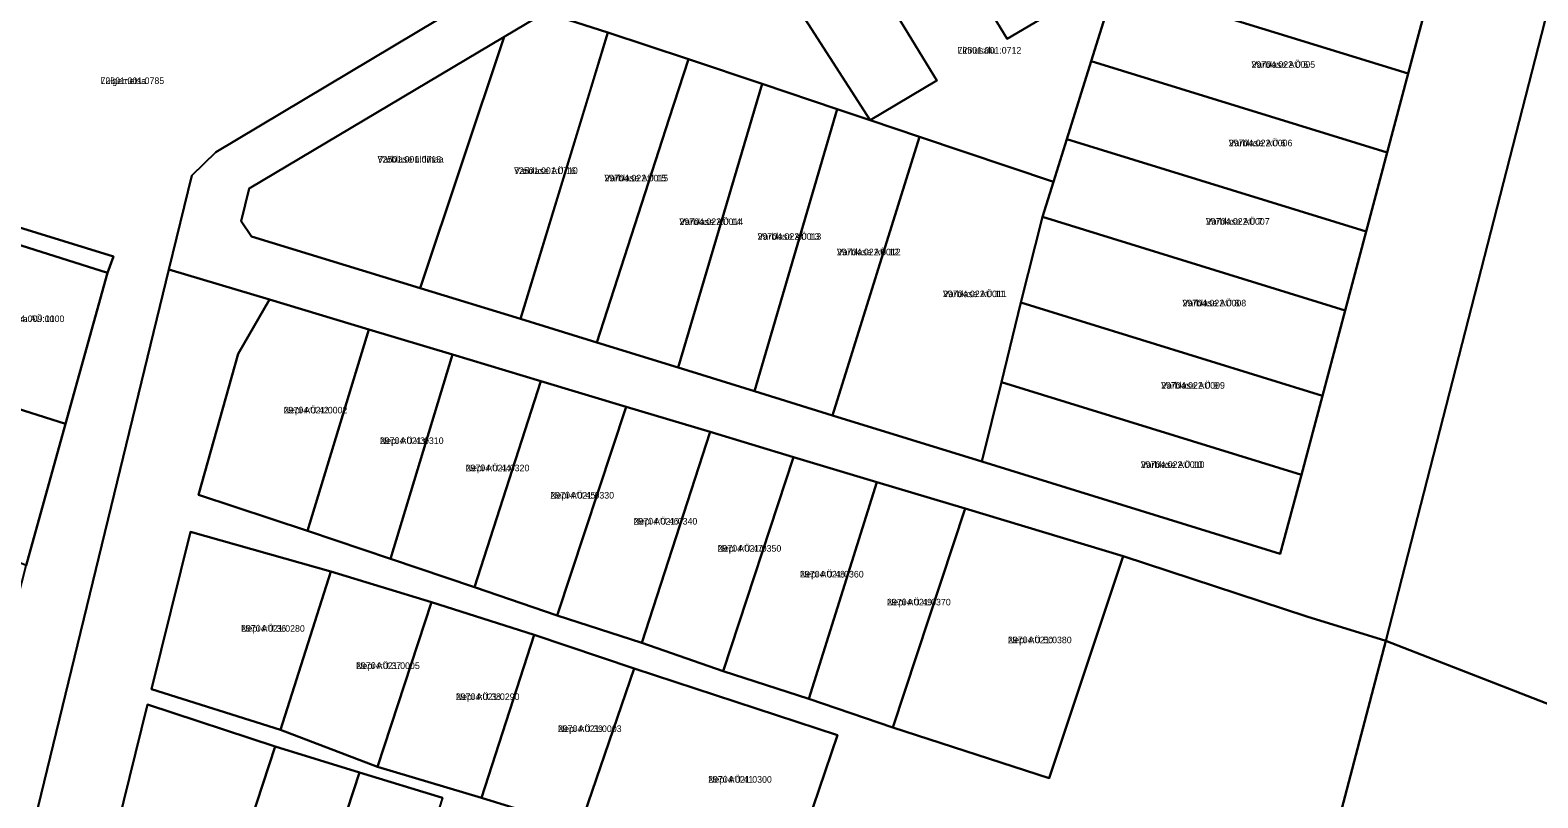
# Model space of a CAD drawing. Extents: x 504287 to 537970, y 6539941 to 6586214.
# Drawn here: x 515935.2 to 516278.4, y 6563085.5 to 6563260.2 of the extents above; entities that cross this region are included whole.
import ezdxf

# ---------------------------------------------------------------- set-up
doc = ezdxf.new("R2010")
doc.units = 0
for name, color, linetype in [('L_AADRESS', 7, 'Continuous'), ('PIIR', 7, 'Continuous'), ('TUNNUS', 7, 'Continuous')]:
    doc.layers.add(name, color=color, linetype=linetype)

msp = doc.modelspace()

# ---------------------------------------------------------------- linework, layer by layer
at = {"layer": 'PIIR'}
for points in [[(515972.01, 6563227.18), (515977.46, 6563232.44), (516073.64, 6563289.98), (516050.45, 6563297.65), (516073.73, 6563311.23), (516084.26, 6563317.42), (516122.11, 6563339.48), (516146.05, 6563353.34), (516182.38, 6563374.75), (516207.94, 6563366.8), (516299.43, 6563338.16), (516243.75, 6563121.25), (516225.77, 6563126.81), (516183.96, 6563140.52), (516148, 6563151.33), (516127.9, 6563157.37), (516108.91, 6563163.08), (516089.94, 6563168.78), (516070.84, 6563174.52), (516051.46, 6563180.35), (516031.31, 6563186.4), (516012.25, 6563192.13), (515989.69, 6563198.92), (515966.79, 6563205.76)], [(516299.43, 6563338.16), (516320.7, 6563333.13), (516451.55, 6563103.15), (516401.08, 6563060.05), (516243.75, 6563121.25)], [(516073.64, 6563289.98), (515977.46, 6563232.44), (515972.01, 6563227.18), (515966.79, 6563205.76), (515909.97, 6562972.61), (515893.26, 6562974.94), (515902.53, 6563013.27), (515910.51, 6563045.99), (515918.12, 6563075.85), (515920.24, 6563083.98), (515927.25, 6563111.02), (515934.26, 6563138.36), (515943.25, 6563170.65), (515952.8, 6563204.98), (515954.15, 6563208.7), (515828.79, 6563247.37), (515836.63, 6563271.97), (515845.75, 6563300.51), (515851.71, 6563319.17), (515917.69, 6563297.46), (515956.39, 6563284.6), (515969.65, 6563324.42), (516015.82, 6563309.11), (516050.45, 6563297.65)], [(516142.3, 6563318.97), (516173.58, 6563267.75), (516157.59, 6563258.26), (516126.3, 6563309.48)], [(516173.58, 6563267.75), (516182.26, 6563270.92), (516176.71, 6563253.19), (516171.16, 6563235.45), (516168.1, 6563225.67), (516137.61, 6563235.94), (516126.37, 6563239.73), (516141.59, 6563248.77), (516110.32, 6563299.97), (516126.3, 6563309.48), (516157.59, 6563258.26)], [(516110.32, 6563299.97), (516141.59, 6563248.77), (516126.37, 6563239.73), (516093.94, 6563290.28)], [(516126.37, 6563239.73), (516118.86, 6563242.26), (516101.78, 6563248.01), (516085.03, 6563253.65), (516066.7, 6563259.68), (516052.39, 6563264.24), (516050.99, 6563264.69), (516093.94, 6563290.28)], [(516253.63, 6563268.32), (516248.84, 6563250.35), (516182.26, 6563270.92), (516183.02, 6563273.35), (516187.81, 6563288.66)], [(516248.84, 6563250.35), (516244.06, 6563232.38), (516176.71, 6563253.19), (516182.26, 6563270.92)], [(516043.06, 6563258.69), (516052.39, 6563264.24), (516066.7, 6563259.68), (516046.78, 6563194.5), (516023.98, 6563201.49)], [(516023.98, 6563201.49), (515985.56, 6563213.28), (515983.2, 6563216.76), (515985.02, 6563224.15), (516043.06, 6563258.69)], [(516062.43, 6563245.69), (516066.7, 6563259.68), (516085.03, 6563253.65), (516080.65, 6563240.11), (516064.16, 6563189.14), (516046.78, 6563194.5)], [(516101.78, 6563248.01), (516082.66, 6563183.42), (516064.16, 6563189.14), (516080.65, 6563240.11), (516085.03, 6563253.65)], [(516244.06, 6563232.38), (516239.27, 6563214.4), (516171.16, 6563235.45), (516176.71, 6563253.19)], [(515828.79, 6563247.37), (515954.15, 6563208.7), (515952.8, 6563204.98), (515915.08, 6563216.94), (515873.94, 6563229.21), (515830.44, 6563242.46), (515826.37, 6563240.09), (515826.78, 6563241.11)], [(516118.86, 6563242.26), (516100.05, 6563178.05), (516082.66, 6563183.42), (516101.78, 6563248.01)], [(516126.37, 6563239.73), (516137.61, 6563235.94), (516117.82, 6563172.56), (516100.05, 6563178.05), (516118.86, 6563242.26)], [(516168.1, 6563225.67), (516165.61, 6563217.71), (516160.72, 6563198.21), (516156.25, 6563180.14), (516151.78, 6563162.06), (516117.82, 6563172.56), (516137.61, 6563235.94)], [(516239.27, 6563214.4), (516234.48, 6563196.43), (516165.61, 6563217.71), (516168.1, 6563225.67), (516171.16, 6563235.45)], [(515903.76, 6563183.26), (515912.83, 6563210.34), (515915.08, 6563216.94), (515952.8, 6563204.98), (515943.25, 6563170.65), (515904.96, 6563182.76)], [(516234.48, 6563196.43), (516229.31, 6563177.01), (516160.72, 6563198.21), (516165.61, 6563217.71)], [(515982.51, 6563186.6), (515989.69, 6563198.92), (516012.25, 6563192.13), (515998.3, 6563146.25), (515973.55, 6563154.51)], [(516229.31, 6563177.01), (516224.53, 6563159.04), (516156.25, 6563180.14), (516160.72, 6563198.21)], [(516012.25, 6563192.13), (516031.31, 6563186.4), (516017.19, 6563139.95), (515998.3, 6563146.25)], [(516031.31, 6563186.4), (516051.46, 6563180.35), (516036.36, 6563133.5), (516017.19, 6563139.95)], [(515914.03, 6563153.48), (515896.73, 6563159.59), (515904.96, 6563182.76), (515943.25, 6563170.65), (515934.26, 6563138.36), (515912.05, 6563147.73)], [(516051.46, 6563180.35), (516070.84, 6563174.52), (516055.15, 6563127.03), (516036.36, 6563133.5)], [(516224.53, 6563159.04), (516219.74, 6563141.07), (516151.78, 6563162.06), (516156.25, 6563180.14)], [(516070.84, 6563174.52), (516089.94, 6563168.78), (516074.41, 6563120.82), (516055.15, 6563127.03)], [(516074.41, 6563120.82), (516089.94, 6563168.78), (516108.91, 6563163.08), (516092.93, 6563114.38)], [(516108.91, 6563163.08), (516127.9, 6563157.37), (516112.44, 6563108.05), (516092.93, 6563114.38)], [(516127.9, 6563157.37), (516148, 6563151.33), (516131.54, 6563101.5), (516112.44, 6563108.05)], [(516148, 6563151.33), (516183.96, 6563140.52), (516167.16, 6563089.97), (516131.54, 6563101.5)], [(515971.71, 6563146.04), (516003.6, 6563137.04), (515992.2, 6563101.02), (515962.81, 6563110.27)], [(516060.23, 6563078.65), (516106.42, 6563062.93), (516118.95, 6563099.81), (516072.69, 6563114.98), (516049.92, 6563122.63), (516026.55, 6563130.04), (516003.6, 6563137.04), (515971.71, 6563146.04), (515962.81, 6563110.27), (515992.2, 6563101.02), (516014.24, 6563092.56), (516037.93, 6563085.55)], [(516003.6, 6563137.04), (516026.55, 6563130.04), (516014.24, 6563092.56), (515992.2, 6563101.02)], [(516026.55, 6563130.04), (516049.92, 6563122.63), (516037.93, 6563085.55), (516014.24, 6563092.56)], [(516049.92, 6563122.63), (516072.69, 6563114.98), (516060.23, 6563078.65), (516037.93, 6563085.55)], [(516131.28, 6562691.84), (516162.69, 6562811.97), (516169.98, 6562839.87), (516172.18, 6562848.28), (516181.49, 6562883.88), (516243.75, 6563121.25), (516401.08, 6563060.05), (516451.55, 6563103.15), (516460.76, 6563084.69), (516429.36, 6563057.64), (516384.12, 6562938.53), (516358.44, 6562814.78), (516531.81, 6562754.14), (516289.98, 6562584.24), (516210.37, 6562653.1)], [(516072.69, 6563114.98), (516118.95, 6563099.81), (516106.42, 6563062.93), (516060.23, 6563078.65)], [(515961.94, 6563106.73), (515990.96, 6563097.2), (515976.94, 6563054.33), (515951.02, 6563062.48)], [(515990.96, 6563097.2), (516010.19, 6563091.3), (515996.15, 6563048.45), (515976.94, 6563054.33)], [(516010.19, 6563091.3), (516029.02, 6563085.5), (516015.32, 6563043.05), (515996.15, 6563048.45)]]:
    msp.add_lwpolyline(points, close=True, dxfattribs=at)
for points in [[(516052.39, 6563264.24), (516043.06, 6563258.69), (515985.02, 6563224.15), (515983.2, 6563216.76), (515985.56, 6563213.28), (516023.98, 6563201.49), (516046.78, 6563194.5), (516064.16, 6563189.14), (516082.66, 6563183.42), (516100.05, 6563178.05), (516117.82, 6563172.56), (516151.78, 6563162.06), (516219.74, 6563141.07), (516224.53, 6563159.04), (516229.31, 6563177.01), (516234.48, 6563196.43), (516239.27, 6563214.4), (516244.06, 6563232.38), (516248.84, 6563250.35), (516253.63, 6563268.32)], [(515909.97, 6562972.61), (515966.79, 6563205.76), (515989.69, 6563198.92), (515982.51, 6563186.6), (515973.55, 6563154.51), (515998.3, 6563146.25), (516017.19, 6563139.95), (516036.36, 6563133.5), (516055.15, 6563127.03), (516074.41, 6563120.82), (516092.93, 6563114.38), (516112.44, 6563108.05), (516131.54, 6563101.5), (516167.16, 6563089.97), (516183.96, 6563140.52), (516225.77, 6563126.81), (516243.75, 6563121.25), (516181.49, 6562883.88)], [(516029.02, 6563085.5), (516010.19, 6563091.3), (515990.96, 6563097.2), (515961.94, 6563106.73), (515951.02, 6563062.48)]]:
    msp.add_lwpolyline(points, dxfattribs=at)

# ---------------------------------------------------------------- texts
at = {"layer": 'L_AADRESS'}
for s, p in [('Linnusalu', (516146.29, 6563254.89)), ('Varblase AÜ 5', (516213.16, 6563251.65)), ('Luigemetsa', (515951.21, 6563247.96)), ('Varblase AÜ 6', (516208, 6563233.79)), ('Varblase üldmaa', (516014.26, 6563230.09)), ('Varblase AÜ 16', (516045.34, 6563227.49)), ('Varblase AÜ 15', (516065.91, 6563225.8)), ('Varblase AÜ 14', (516082.97, 6563215.87)), ('Varblase AÜ 7', (516202.81, 6563215.94)), ('Varblase AÜ 13', (516100.76, 6563212.52)), ('Varblase AÜ 12', (516118.83, 6563208.98)), ('Varblase AÜ 11', (516142.96, 6563199.46)), ('Varblase AÜ 8', (516197.47, 6563197.36)), ('Kajaka AÜ 10', (515928.49, 6563193.79)), ('Varblase AÜ 9', (516192.62, 6563178.62)), ('Nepi AÜ 42', (515992.9, 6563173)), ('Nepi AÜ 43', (516014.8, 6563166.05)), ('Nepi AÜ 44', (516034.32, 6563159.84)), ('Varblase AÜ 10', (516187.98, 6563160.61)), ('Nepi AÜ 45', (516053.6, 6563153.63)), ('Nepi AÜ 46', (516072.54, 6563147.71)), ('Nepi AÜ 47', (516091.66, 6563141.54)), ('Nepi AÜ 48', (516110.41, 6563135.67)), ('Nepi AÜ 49', (516130.22, 6563129.31)), ('Nepi AÜ 36', (515983.21, 6563123.32)), ('Nepi AÜ 50', (516157.75, 6563120.71)), ('Nepi AÜ 37', (516009.38, 6563114.85)), ('Nepi AÜ 38', (516032.08, 6563107.78)), ('Nepi AÜ 39', (516055.31, 6563100.5)), ('Nepi AÜ 41', (516089.51, 6563088.96))]:
    msp.add_text(s, height=1.5, dxfattribs=at).set_placement(p)
at = {"layer": 'TUNNUS'}
for s, p in [('72501:001:0712', (516146.29, 6563254.89)), ('29704:022:0005', (516213.16, 6563251.65)), ('72601:001:0785', (515951.21, 6563247.96)), ('29704:022:0006', (516208, 6563233.79)), ('72501:001:0713', (516014.26, 6563230.09)), ('72501:001:0710', (516045.34, 6563227.49)), ('29704:022:0015', (516065.91, 6563225.8)), ('29704:022:0014', (516082.97, 6563215.87)), ('29704:022:0007', (516202.81, 6563215.94)), ('29704:022:0013', (516100.76, 6563212.52)), ('29704:022:0012', (516118.83, 6563208.98)), ('29704:022:0011', (516142.96, 6563199.46)), ('29704:022:0008', (516197.47, 6563197.36)), ('29704:009:0100', (515928.49, 6563193.79)), ('29704:022:0009', (516192.62, 6563178.62)), ('29704:021:0002', (515992.9, 6563173)), ('29704:021:0310', (516014.8, 6563166.05)), ('29704:021:0320', (516034.32, 6563159.84)), ('29704:022:0010', (516187.98, 6563160.61)), ('29704:021:0330', (516053.6, 6563153.63)), ('29704:021:0340', (516072.54, 6563147.71)), ('29704:021:0350', (516091.66, 6563141.54)), ('29704:021:0360', (516110.41, 6563135.67)), ('29704:021:0370', (516130.22, 6563129.31)), ('29704:021:0280', (515983.21, 6563123.32)), ('29704:021:0380', (516157.75, 6563120.71)), ('29704:021:0005', (516009.38, 6563114.85)), ('29704:021:0290', (516032.08, 6563107.78)), ('29704:021:0003', (516055.31, 6563100.5)), ('29704:021:0300', (516089.51, 6563088.96))]:
    msp.add_text(s, height=1.5, dxfattribs=at).set_placement(p)

doc.saveas('drawing.dxf')
